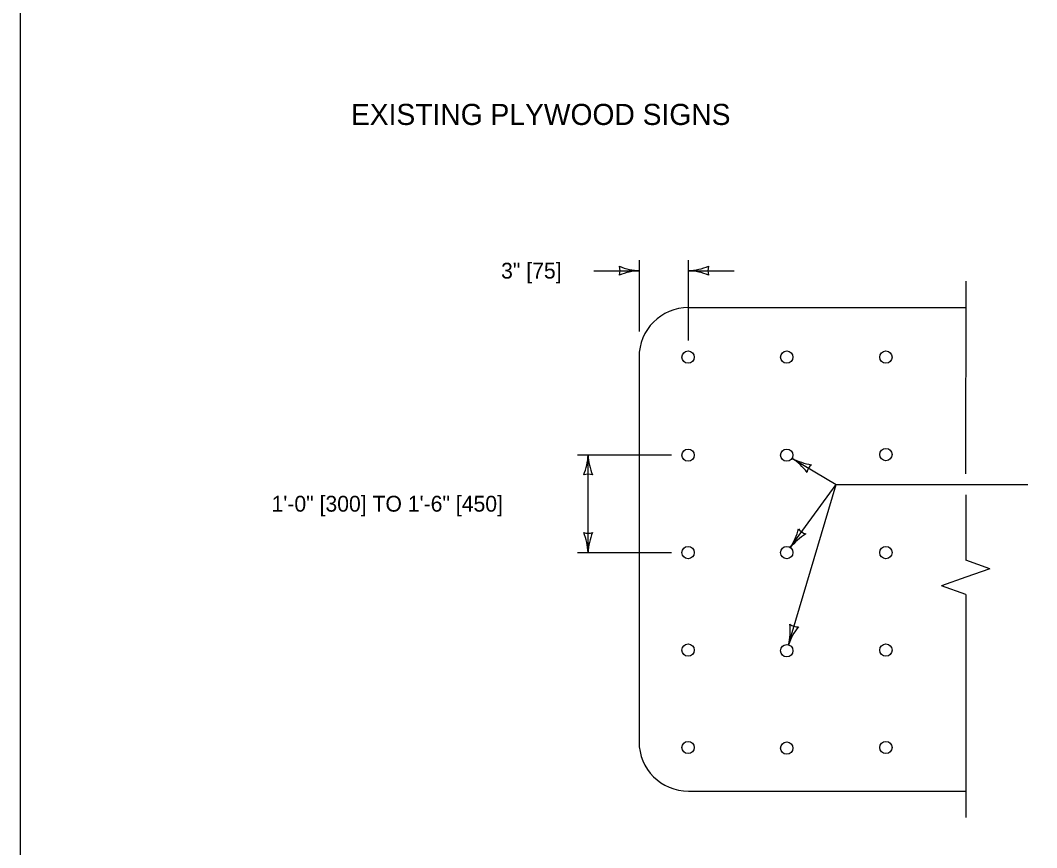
# Model space of a CAD drawing. Extents: x 49991.4 to 50021, y 49987.6 to 50011.4.
# Drawn here: x 50000.336 to 50004.187, y 50004.566 to 50007.7 of the extents above; entities that cross this region are included whole.
import ezdxf

# ---------------------------------------------------------------- set-up
doc = ezdxf.new("R2010")
doc.units = 0
for name, color, linetype in [('Level 1', 7, 'Continuous'), ('Level 2', 7, 'Continuous'), ('Level 3', 7, 'Continuous'), ('Level 6', 7, 'Continuous')]:
    doc.layers.add(name, color=color, linetype=linetype)

msp = doc.modelspace()

# ---------------------------------------------------------------- linework, layer by layer
at = {"layer": 'Level 1'}
for p, q in [((50002.8678, 50006.6119), (50003.9184, 50006.6119)), ((50002.6803, 50006.4243), (50002.6803, 50004.9675)), ((50002.8678, 50004.78), (50003.9184, 50004.78))]:
    msp.add_line(p, q, dxfattribs=at)
msp.add_lwpolyline([(50008.6146, 50011.2628), (50000.3356, 50011.2628), (50000.3356, 50000.0624), (50008.6146, 50000.0624)], close=True, dxfattribs=at)
for centre in [(50002.8662, 50006.4246), (50003.24, 50006.4246), (50003.6163, 50006.4246), (50002.8662, 50006.053), (50003.24, 50006.053), (50003.6163, 50006.0554), (50002.8662, 50005.6838), (50003.24, 50005.6838), (50003.6163, 50005.6838), (50002.8662, 50005.3147), (50003.24, 50005.3123), (50003.6163, 50005.3147), (50002.8662, 50004.9455), (50003.24, 50004.9431), (50003.6163, 50004.9455)]:
    msp.add_circle(centre, 0.0233, dxfattribs=at)
for centre, start, end in [((50002.8678, 50006.4244), 90, 180), ((50002.8678, 50004.9675), 180, 270)]:
    msp.add_arc(centre, 0.1875, start, end, dxfattribs=at)
at = {"layer": 'Level 3'}
for p, q in [((50002.6821, 50006.521), (50002.6821, 50006.7919)), ((50002.8678, 50006.4878), (50002.8678, 50006.7919)), ((50002.5087, 50006.7519), (50002.6821, 50006.7519)), ((50002.8678, 50006.7519), (50003.0412, 50006.7519)), ((50002.4475, 50006.0541), (50002.8029, 50006.0541)), ((50002.4875, 50005.6838), (50002.4875, 50006.0541)), ((50003.2601, 50006.0412), (50003.4271, 50005.9422)), ((50003.2467, 50005.3346), (50003.4271, 50005.9422)), ((50003.2537, 50005.7027), (50003.4271, 50005.9422)), ((50003.4271, 50005.9422), (50004.1537, 50005.9423)), ((50002.4475, 50005.6838), (50002.8029, 50005.6838))]:
    msp.add_line(p, q, dxfattribs=at)
for centre, radius, start, end in [((50002.6913, 50006.974), 0.2223, 247.456, 267.6395), ((50002.5539, 50006.7519), 0.0548, 342.1388, 17.8612), ((50002.8563, 50006.9846), 0.233, 272.8273, 292.0772), ((50002.996, 50006.7519), 0.0548, 162.1388, 197.8612), ((50002.6936, 50006.5192), 0.233, 92.8273, 112.0772), ((50002.8586, 50006.5298), 0.2223, 67.456, 87.6395), ((50002.2654, 50006.0633), 0.2223, 337.456, 357.6395), ((50002.7202, 50006.0656), 0.233, 182.8273, 202.0772), ((50003.139, 50005.8547), 0.2223, 36.8098, 56.9933), ((50003.3688, 50006.2472), 0.233, 242.1811, 261.4309), ((50003.3704, 50005.9758), 0.0548, 131.4926, 167.2149), ((50002.4875, 50005.9259), 0.0548, 72.1388, 107.8612), ((50002.4875, 50005.812), 0.0548, 252.1388, 287.8612), ((50002.2548, 50005.6723), 0.233, 2.8273, 22.0772), ((50002.7096, 50005.6746), 0.2223, 157.456, 177.6395), ((50003.0585, 50005.8298), 0.233, 326.9274, 346.1772), ((50003.4283, 50005.565), 0.2223, 121.5561, 141.7396), ((50003.3289, 50005.8065), 0.0548, 216.2389, 251.9612), ((50003.0203, 50005.3898), 0.233, 346.2897, 5.5395), ((50003.2832, 50005.4575), 0.0548, 235.6012, 271.3235), ((50003.457, 50005.2626), 0.2223, 140.9184, 161.1019)]:
    msp.add_arc(centre, radius, start, end, dxfattribs=at)
at = {"layer": 'Level 6'}
for p, q in [((50003.9184, 50006.7119), (50003.9182, 50005.9822)), ((50003.9186, 50005.9022), (50003.9184, 50005.655)), ((50004.0098, 50005.6226), (50003.9184, 50005.655)), ((50004.0098, 50005.6226), (50003.9184, 50005.5902)), ((50003.9184, 50005.5902), (50003.827, 50005.5578)), ((50003.9184, 50005.5254), (50003.827, 50005.5578)), ((50003.9184, 50005.5254), (50003.9184, 50004.68))]:
    msp.add_line(p, q, dxfattribs=at)

# ---------------------------------------------------------------- texts
at = {"layer": 'Level 2'}
for s, height, p in [('EXISTING PLYWOOD SIGNS', 0.08, (50001.5885, 50007.3039)), ('3" [75]', 0.06, (50002.1576, 50006.7219)), ('1\'-0" [300] TO 1\'-6" [450]', 0.06, (50001.2876, 50005.839))]:
    msp.add_text(s, height=height, dxfattribs=at).set_placement(p)

doc.saveas('drawing.dxf')
